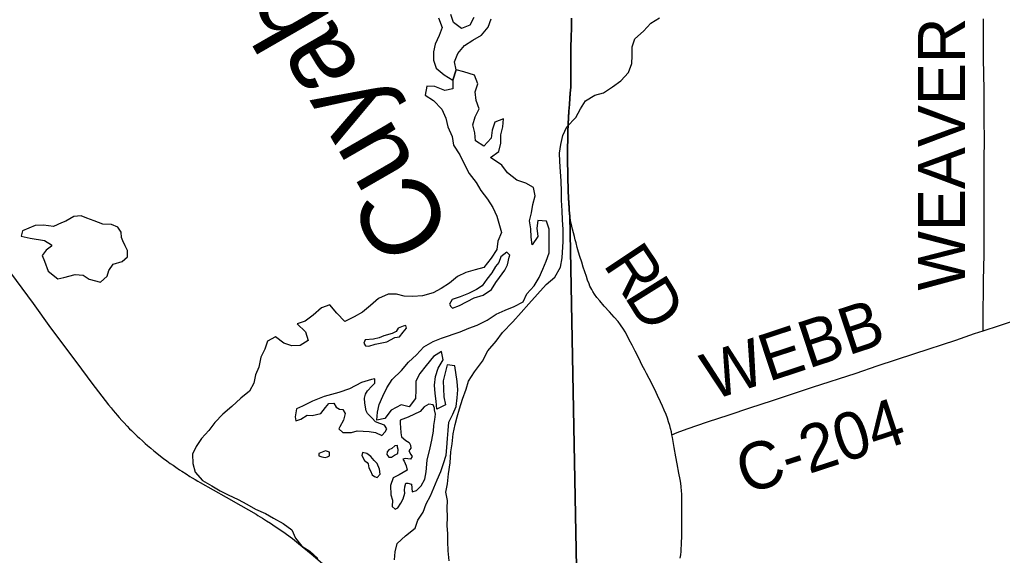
# Model space of a CAD drawing. Extents: x 0 to 34, y 0 to 22.
# Drawn here: x 4.363 to 5.549, y 18.065 to 18.712 of the extents above; entities that cross this region are included whole.
import ezdxf

# ---------------------------------------------------------------- set-up
doc = ezdxf.new("R2010")
doc.units = 0
for name, color, linetype in [('GM_X_Corporation', 7, 'Continuous'), ('GM_X_County_Road', 7, 'Continuous'), ('GM_X_County_Road_Text', 7, 'Continuous'), ('GM_X_Major_Lake', 7, 'Continuous'), ('GM_X_Major_River', 7, 'Continuous'), ('GM_X_Major_River_Text', 7, 'Continuous'), ('GM_X_Minor_Lake', 7, 'Continuous'), ('GM_X_Minor_River', 7, 'Continuous'), ('GM_X_State_Route', 7, 'Continuous'), ('GM_X_Township_Road', 7, 'Continuous'), ('GM_X_Township_Road_Text', 7, 'Continuous')]:
    doc.layers.add(name, color=color, linetype=linetype)

msp = doc.modelspace()

# ---------------------------------------------------------------- linework, layer by layer
at = {"layer": 'GM_X_Corporation'}
for points in [[(5.0372, 17.9657), (5.0273, 18.4749), (5.0269, 18.4781), (5.0266, 18.4816), (5.0264, 18.4849), (5.026, 18.4907), (5.0257, 18.4966), (5.0254, 18.5052), (5.0252, 18.5098), (5.025, 18.5176), (5.0249, 18.5239), (5.0248, 18.5304), (5.0247, 18.5364), (5.0247, 18.5429), (5.0247, 18.548), (5.0247, 18.5561), (5.0248, 18.5679), (5.025, 18.5766), (5.0254, 18.5856), (5.0258, 18.5939), (5.0263, 18.6011), (5.0269, 18.6094), (5.0275, 18.6171), (5.0279, 18.6231), (5.0284, 18.6303), (5.0286, 18.6362), (5.0287, 18.641), (5.0287, 18.6468), (5.0286, 18.6519), (5.0285, 18.6576), (5.0284, 18.6614), (5.0284, 18.6675), (5.0284, 18.6713), (5.0285, 18.6794), (5.0288, 18.6892), (5.0292, 18.7031), (5.0294, 18.7134)], [(5.0372, 17.9657), (5.0273, 18.4749), (5.0269, 18.4781), (5.0266, 18.4816), (5.0264, 18.4849), (5.026, 18.4907), (5.0257, 18.4966), (5.0254, 18.5052), (5.0252, 18.5098), (5.025, 18.5176), (5.0249, 18.5239), (5.0248, 18.5304), (5.0247, 18.5364), (5.0247, 18.5429), (5.0247, 18.548), (5.0247, 18.5561), (5.0248, 18.5679), (5.025, 18.5766), (5.0254, 18.5856), (5.0258, 18.5939), (5.0263, 18.6011), (5.0269, 18.6094), (5.0275, 18.6171), (5.0279, 18.6231), (5.0284, 18.6303), (5.0286, 18.6362), (5.0287, 18.641), (5.0287, 18.6468), (5.0286, 18.6519), (5.0285, 18.6576), (5.0284, 18.6614), (5.0284, 18.6675), (5.0284, 18.6713), (5.0285, 18.6794), (5.0288, 18.6892), (5.0292, 18.7031), (5.0294, 18.7134)], [(5.0294, 18.7134), (5.0292, 18.7031), (5.0288, 18.6892), (5.0285, 18.6794), (5.0284, 18.6713), (5.0284, 18.6675), (5.0284, 18.6614), (5.0285, 18.6576), (5.0286, 18.6519), (5.0287, 18.6468), (5.0287, 18.641), (5.0286, 18.6362), (5.0284, 18.6303), (5.0279, 18.6231), (5.0275, 18.6171), (5.0269, 18.6094), (5.0263, 18.6011), (5.0258, 18.5939), (5.0254, 18.5856), (5.025, 18.5766), (5.0248, 18.5679), (5.0247, 18.5561), (5.0247, 18.548), (5.0247, 18.5429), (5.0247, 18.5364), (5.0248, 18.5304), (5.0249, 18.5239), (5.025, 18.5176), (5.0252, 18.5098), (5.0254, 18.5052), (5.0257, 18.4966), (5.026, 18.4907), (5.0264, 18.4849), (5.0266, 18.4816), (5.0269, 18.4781), (5.0273, 18.4749), (5.0372, 17.9657)]]:
    msp.add_lwpolyline(points, dxfattribs=at)
at = {"layer": 'GM_X_County_Road'}
for points in [[(5.5262, 18.3362), (5.5263, 18.348), (5.5267, 18.3971), (5.5273, 18.4282), (5.5274, 18.4517), (5.5275, 18.4853), (5.5276, 18.499), (5.5276, 18.5419), (5.5278, 18.5679), (5.5276, 18.5897), (5.5273, 18.6313), (5.5272, 18.6413), (5.5267, 18.6692), (5.5266, 18.6847), (5.5265, 18.7126)], [(5.5262, 18.3362), (5.5459, 18.3425), (5.6054, 18.3624)], [(5.1506, 18.2108), (5.1571, 18.2134), (5.1691, 18.2178), (5.1935, 18.2262), (5.2196, 18.235), (5.2448, 18.2434), (5.272, 18.2523), (5.3033, 18.2624), (5.3204, 18.2682), (5.373, 18.2853), (5.3983, 18.294), (5.4437, 18.309), (5.4934, 18.3251), (5.5157, 18.3328), (5.5262, 18.3362)]]:
    msp.add_lwpolyline(points, dxfattribs=at)
at = {"layer": 'GM_X_Major_Lake'}
for p, q in [((4.8901, 18.651), (4.8861, 18.6387)), ((4.8901, 18.651), (4.8861, 18.6387)), ((4.9333, 18.4062), (4.927, 18.3986)), ((4.8128, 18.3328), (4.803, 18.3301)), ((4.8469, 18.239), (4.8321, 18.2321)), ((4.7706, 18.2157), (4.785, 18.2147)), ((4.7319, 18.1832), (4.7349, 18.1843)), ((4.8124, 18.1944), (4.809, 18.1925)), ((4.7841, 18.1756), (4.7846, 18.171))]:
    msp.add_line(p, q, dxfattribs=at)
for points in [[(4.9452, 18.5359), (4.9318, 18.5455), (4.9415, 18.5525), (4.9441, 18.5628), (4.944, 18.5726), (4.9465, 18.5825), (4.9472, 18.592), (4.937, 18.5881), (4.9337, 18.5782), (4.9326, 18.5687), (4.9237, 18.5591), (4.9137, 18.5655), (4.9125, 18.5749), (4.9101, 18.5848), (4.913, 18.5943), (4.9179, 18.6039), (4.9143, 18.6141), (4.9131, 18.6247), (4.9164, 18.6342), (4.9121, 18.6448), (4.8996, 18.6488), (4.8901, 18.651)], [(4.8861, 18.6387), (4.8862, 18.6281), (4.8764, 18.6261), (4.8646, 18.631), (4.8548, 18.6313), (4.8526, 18.6206), (4.8629, 18.6143), (4.8728, 18.6037), (4.8778, 18.5928), (4.8801, 18.5822), (4.8852, 18.5708)], [(4.8852, 18.5708), (4.8871, 18.5602), (4.8944, 18.5485), (4.9002, 18.5368), (4.9059, 18.5262), (4.9143, 18.5153), (4.9201, 18.5055), (4.9281, 18.4949), (4.9343, 18.4851), (4.9393, 18.4745), (4.9447, 18.4549), (4.9403, 18.4442), (4.9392, 18.4343), (4.9325, 18.424), (4.9235, 18.4126), (4.9133, 18.4099), (4.9019, 18.4064), (4.8918, 18.4017), (4.882, 18.3937), (4.8722, 18.3872), (4.8624, 18.3822), (4.8496, 18.3783), (4.8378, 18.3778), (4.8276, 18.3781), (4.8181, 18.3803), (4.8079, 18.3806), (4.7966, 18.3752), (4.7868, 18.3668), (4.777, 18.3587), (4.7669, 18.353), (4.7559, 18.3476), (4.746, 18.3577), (4.7376, 18.3675), (4.7278, 18.364), (4.7177, 18.3549), (4.7079, 18.348), (4.6981, 18.3448), (4.7083, 18.3351), (4.7115, 18.3245), (4.7017, 18.3183), (4.6918, 18.3182), (4.682, 18.3212), (4.6721, 18.3291), (4.6623, 18.3237), (4.6593, 18.3142), (4.6545, 18.3043), (4.6519, 18.2925), (4.6478, 18.283), (4.646, 18.2731), (4.6408, 18.2636), (4.6303, 18.2548), (4.6194, 18.2449), (4.6084, 18.2357), (4.5987, 18.2257), (4.5916, 18.2158), (4.5826, 18.2063), (4.5762, 18.1967), (4.5721, 18.1872), (4.5722, 18.1762), (4.5753, 18.1656), (4.5841, 18.1558), (4.5951, 18.1491), (4.6054, 18.1431), (4.6149, 18.1383), (4.627, 18.1327), (4.6377, 18.1271), (4.6479, 18.1211), (4.6601, 18.1158), (4.6696, 18.1102), (4.6814, 18.1039), (4.6917, 18.096), (4.6963, 18.0862), (4.7039, 18.0764), (4.7134, 18.0704), (4.7233, 18.0617)], [(4.8159, 18.06), (4.8166, 18.0695), (4.8191, 18.0798), (4.8292, 18.089), (4.8405, 18.0983), (4.8438, 18.1078), (4.8505, 18.1174), (4.8538, 18.1273), (4.859, 18.1372), (4.8634, 18.1468), (4.8671, 18.1563), (4.8716, 18.1666), (4.8749, 18.1762), (4.8781, 18.1861), (4.8788, 18.1956), (4.8798, 18.2062), (4.8805, 18.2161), (4.8815, 18.226), (4.8863, 18.2355), (4.89, 18.2451), (4.8914, 18.2553), (4.892, 18.2652), (4.8912, 18.2751), (4.8887, 18.294), (4.8792, 18.2951), (4.877, 18.2856), (4.8745, 18.276), (4.875, 18.2662), (4.8751, 18.2567), (4.8771, 18.2468), (4.8669, 18.2418), (4.8661, 18.2512), (4.8648, 18.2607), (4.8639, 18.2706), (4.8653, 18.2809), (4.8686, 18.2911), (4.8746, 18.3011), (4.8726, 18.3113), (4.8628, 18.3051), (4.8538, 18.2944), (4.8464, 18.2848), (4.8416, 18.2753), (4.8413, 18.265), (4.841, 18.2544), (4.8336, 18.2444), (4.8237, 18.2469), (4.8116, 18.2404), (4.8042, 18.2304), (4.7944, 18.2284), (4.7954, 18.2379), (4.7972, 18.2474), (4.8016, 18.2573), (4.8064, 18.2676), (4.8131, 18.2776), (4.824, 18.2883), (4.8326, 18.2983), (4.8423, 18.3072), (4.8513, 18.3168), (4.8626, 18.3234), (4.8724, 18.3273), (4.895, 18.3351), (4.9056, 18.3394), (4.9154, 18.343), (4.9274, 18.3492), (4.9383, 18.3565), (4.9493, 18.3612), (4.9602, 18.3655), (4.9711, 18.3713), (4.9756, 18.3809), (4.9842, 18.3905), (4.9905, 18.4004), (4.9949, 18.4107), (4.9986, 18.4203), (5.0023, 18.4302), (5.0026, 18.4397), (5.0023, 18.4587), (4.9992, 18.4685), (4.9886, 18.4695), (4.9876, 18.46), (4.9888, 18.4502), (4.9817, 18.4398), (4.9805, 18.4493), (4.9804, 18.4592), (4.9787, 18.469), (4.9809, 18.4785), (4.9827, 18.4888), (4.9856, 18.4991), (4.9836, 18.509), (4.9741, 18.5145), (4.9634, 18.5178), (4.9523, 18.5268), (4.9452, 18.5359)], [(4.927, 18.3986), (4.9217, 18.3906), (4.9146, 18.386), (4.9052, 18.3813), (4.895, 18.3771), (4.8855, 18.374), (4.8822, 18.3683), (4.8837, 18.3656), (4.8856, 18.3634), (4.8943, 18.3668), (4.912, 18.3761), (4.9226, 18.3792), (4.9328, 18.3861), (4.938, 18.3945), (4.9425, 18.4006), (4.9488, 18.4094), (4.9522, 18.4158), (4.954, 18.425), (4.9551, 18.4276), (4.9513, 18.431), (4.9442, 18.4253), (4.9416, 18.4188), (4.9375, 18.4138), (4.9333, 18.4062)], [(4.803, 18.3301), (4.7973, 18.3278), (4.7905, 18.3262), (4.7803, 18.3254), (4.7788, 18.3212), (4.7808, 18.3182), (4.7849, 18.3175), (4.7925, 18.3202), (4.8065, 18.3229), (4.8163, 18.3283), (4.8216, 18.3291), (4.8264, 18.3345), (4.8302, 18.3394), (4.8294, 18.3425), (4.826, 18.3417), (4.8203, 18.3393), (4.8177, 18.3352), (4.8128, 18.3328)], [(4.785, 18.2147), (4.7929, 18.2136), (4.8005, 18.2099), (4.8043, 18.2144), (4.8065, 18.2179), (4.8038, 18.2224), (4.7981, 18.2243), (4.7928, 18.2265), (4.7886, 18.231), (4.7833, 18.2363), (4.7814, 18.2397), (4.7798, 18.2491), (4.7794, 18.2548), (4.7808, 18.2598), (4.7831, 18.264), (4.7883, 18.2693), (4.7921, 18.2731), (4.7921, 18.2781), (4.7879, 18.2773), (4.7758, 18.2738), (4.7615, 18.2661), (4.7487, 18.2618), (4.7309, 18.2571), (4.7166, 18.2513), (4.7045, 18.2455), (4.6973, 18.2421), (4.6959, 18.2326), (4.6967, 18.2276), (4.7027, 18.2296), (4.7103, 18.2346), (4.7163, 18.2339), (4.7269, 18.2366), (4.7325, 18.2438), (4.7363, 18.2484), (4.7427, 18.2489), (4.7454, 18.2439), (4.7492, 18.2417), (4.7534, 18.2414), (4.756, 18.2364), (4.7542, 18.2285), (4.7497, 18.2205), (4.7486, 18.2178), (4.7532, 18.2137), (4.7638, 18.2137), (4.7706, 18.2157)], [(4.8321, 18.2321), (4.8227, 18.2286), (4.8227, 18.2244), (4.8228, 18.2195), (4.8232, 18.2131), (4.824, 18.2085), (4.8293, 18.204), (4.8335, 18.2014), (4.8351, 18.1984), (4.8355, 18.1946), (4.8332, 18.1915), (4.8355, 18.187), (4.8371, 18.1847), (4.8352, 18.1813), (4.8287, 18.182), (4.8257, 18.1812), (4.8273, 18.179), (4.83, 18.1733), (4.8311, 18.168), (4.8213, 18.1626), (4.8142, 18.1588), (4.8108, 18.1496), (4.8113, 18.1383), (4.8132, 18.1318), (4.8129, 18.1242), (4.8167, 18.1209), (4.8197, 18.1228), (4.8235, 18.1281), (4.8261, 18.1334), (4.8283, 18.1403), (4.8279, 18.1441), (4.8283, 18.1479), (4.8294, 18.1524), (4.832, 18.1525), (4.8362, 18.1513), (4.837, 18.1419), (4.8423, 18.1434), (4.8479, 18.1492), (4.8524, 18.1572), (4.8539, 18.1659), (4.8553, 18.1803), (4.8589, 18.1951), (4.8607, 18.2043), (4.8629, 18.2153), (4.8633, 18.2221), (4.8643, 18.2293), (4.8654, 18.2358), (4.8642, 18.2407), (4.8639, 18.243), (4.8623, 18.2471), (4.857, 18.2478), (4.8517, 18.2444), (4.8469, 18.239)], [(4.809, 18.1925), (4.8067, 18.1902), (4.8064, 18.1868), (4.8087, 18.1838), (4.8121, 18.1838), (4.8158, 18.1861), (4.8196, 18.188), (4.82, 18.1929), (4.8192, 18.196), (4.8192, 18.1979), (4.8161, 18.1975), (4.8124, 18.1944)], [(4.7349, 18.1843), (4.7371, 18.1855), (4.7371, 18.19), (4.7325, 18.1915), (4.7246, 18.188), (4.7243, 18.1854), (4.7281, 18.1843), (4.7319, 18.1832)], [(4.7846, 18.171), (4.7869, 18.1673), (4.7888, 18.1624), (4.7918, 18.1605), (4.7949, 18.1594), (4.7986, 18.1632), (4.7978, 18.1693), (4.7947, 18.1761), (4.7913, 18.1798), (4.7871, 18.1847), (4.7825, 18.1881), (4.7772, 18.1892), (4.7765, 18.1858), (4.7796, 18.1797), (4.7826, 18.1775), (4.7841, 18.1756)]]:
    msp.add_lwpolyline(points, dxfattribs=at)
at = {"layer": 'GM_X_Major_River'}
msp.add_line((4.8861, 18.6387), (4.8901, 18.651), dxfattribs=at)
msp.add_line((4.8861, 18.6387), (4.8901, 18.651), dxfattribs=at)
for points in [[(4.9113, 18.7144), (4.9068, 18.7049), (4.8966, 18.701), (4.8871, 18.7082), (4.8836, 18.718)], [(4.8689, 18.7137), (4.8732, 18.702), (4.8698, 18.6925), (4.865, 18.6822), (4.8628, 18.6727), (4.8629, 18.6628), (4.866, 18.653), (4.8755, 18.6451), (4.8861, 18.6387)], [(4.8901, 18.651), (4.8881, 18.6608), (4.8921, 18.6708), (4.9003, 18.6804), (4.9101, 18.6869), (4.9206, 18.6931), (4.9289, 18.7027), (4.9325, 18.7126)]]:
    msp.add_lwpolyline(points, dxfattribs=at)
at = {"layer": 'GM_X_Minor_Lake'}
msp.add_line((4.4636, 18.4648), (4.4534, 18.4689), dxfattribs=at)
msp.add_lwpolyline([(4.4534, 18.4689), (4.4443, 18.4722), (4.4374, 18.4748), (4.4287, 18.474), (4.4189, 18.4686), (4.414, 18.4667), (4.4042, 18.462), (4.3921, 18.4638), (4.3819, 18.4634), (4.3668, 18.4568), (4.365, 18.4504), (4.3759, 18.4482), (4.3934, 18.4453), (4.4017, 18.44), (4.4018, 18.4385), (4.3954, 18.4335), (4.3905, 18.427), (4.3932, 18.4202), (4.3978, 18.4081), (4.4093, 18.3991), (4.4168, 18.4007), (4.4304, 18.4042), (4.4399, 18.4035), (4.4471, 18.3986), (4.4608, 18.395), (4.469, 18.4022), (4.4709, 18.4091), (4.4761, 18.4167), (4.4871, 18.4198), (4.4934, 18.4256), (4.4934, 18.4331), (4.4907, 18.4388), (4.488, 18.4449), (4.4864, 18.449), (4.486, 18.4551), (4.4818, 18.4611), (4.4742, 18.4645), (4.4636, 18.4648)], dxfattribs=at)
at = {"layer": 'GM_X_Minor_River'}
for points in [[(5.0162, 18.4129), (5.018, 18.4243), (5.0194, 18.444), (5.0192, 18.4585), (5.0184, 18.4702), (5.0183, 18.4808), (5.0175, 18.4937), (5.0174, 18.504), (5.0169, 18.5172), (5.0161, 18.5282), (5.0152, 18.5404), (5.0147, 18.5506), (5.0166, 18.5612), (5.0191, 18.5719), (5.0236, 18.5825), (5.0345, 18.5936), (5.0404, 18.6039), (5.0464, 18.6138), (5.0577, 18.6207), (5.0679, 18.6234), (5.0788, 18.6307), (5.089, 18.638), (5.098, 18.648), (5.1021, 18.6586), (5.1028, 18.6681), (5.1027, 18.6787), (5.106, 18.6886), (5.1162, 18.6978), (5.1252, 18.7073), (5.1357, 18.7139)], [(4.8816, 18.0588), (4.8807, 18.0709), (4.8802, 18.0819), (4.8802, 18.0914), (4.8793, 18.1012), (4.8796, 18.1115), (4.8792, 18.1221), (4.8799, 18.1316), (4.8775, 18.1414), (4.8797, 18.1517), (4.8811, 18.1635), (4.8829, 18.1771), (4.8836, 18.1904), (4.8854, 18.1999), (4.8864, 18.212), (4.889, 18.2231), (4.8912, 18.2326), (4.8941, 18.2421), (4.8978, 18.2538), (4.9023, 18.266), (4.9049, 18.2755), (4.9123, 18.2866), (4.9221, 18.2995), (4.9284, 18.3121), (4.9385, 18.3236), (4.946, 18.3342), (4.9584, 18.3469), (4.9685, 18.3583), (4.9779, 18.3686), (4.9884, 18.3805), (4.9989, 18.3919), (5.0091, 18.4011), (5.0162, 18.4129)]]:
    msp.add_lwpolyline(points, dxfattribs=at)
at = {"layer": 'GM_X_State_Route'}
msp.add_lwpolyline([(4.3327, 18.4325), (4.3796, 18.369), (4.4006, 18.3397), (4.4323, 18.2974), (4.4504, 18.2729), (4.4706, 18.2469), (4.4736, 18.2433), (4.4761, 18.2402), (4.4788, 18.2369), (4.481, 18.2345), (4.4835, 18.2316), (4.4866, 18.228), (4.4891, 18.2254), (4.4931, 18.2212), (4.496, 18.2181), (4.4983, 18.2159), (4.5027, 18.2115), (4.5053, 18.209), (4.508, 18.2065), (4.5115, 18.2033), (4.5149, 18.2002), (4.5176, 18.1979), (4.5216, 18.1945), (4.5252, 18.1913), (4.529, 18.1884), (4.5335, 18.1848), (4.5371, 18.1821), (4.5409, 18.1794), (4.545, 18.1763), (4.5484, 18.174), (4.5519, 18.1716), (4.5562, 18.1686), (4.5591, 18.1668), (4.5643, 18.1635), (4.5688, 18.1606), (4.5715, 18.159), (4.5752, 18.1568), (4.5785, 18.1548), (4.581, 18.1533), (4.6124, 18.1356), (4.6303, 18.1255), (4.6486, 18.1148), (4.6508, 18.1134), (4.6534, 18.1119), (4.6563, 18.1101), (4.6587, 18.1086), (4.6612, 18.107), (4.666, 18.104), (4.6689, 18.1021), (4.674, 18.0987), (4.681, 18.094), (4.6927, 18.0856), (4.7, 18.0798), (4.7153, 18.067), (4.754, 18.0338)], dxfattribs=at)
at = {"layer": 'GM_X_Township_Road'}
for points in [[(5.0275, 18.4743), (5.0271, 18.4776), (5.0268, 18.4811), (5.0266, 18.4843), (5.0262, 18.4902), (5.0259, 18.4961), (5.0256, 18.5046), (5.0254, 18.5093), (5.0252, 18.517), (5.0251, 18.5234), (5.025, 18.5299), (5.0249, 18.5358), (5.0249, 18.5423), (5.0249, 18.5475), (5.0249, 18.5556), (5.025, 18.5674), (5.0252, 18.5761), (5.0256, 18.585), (5.026, 18.5934), (5.0265, 18.6006), (5.0271, 18.6088), (5.0278, 18.6165), (5.0281, 18.6226), (5.0286, 18.6297), (5.0288, 18.6356), (5.0289, 18.6404), (5.0289, 18.6462), (5.0289, 18.6514), (5.0287, 18.657), (5.0286, 18.6609), (5.0286, 18.6669), (5.0286, 18.6707), (5.0287, 18.6788), (5.029, 18.6886), (5.0294, 18.7025), (5.0297, 18.7128)], [(5.1506, 18.2108), (5.1499, 18.2142), (5.149, 18.2182), (5.148, 18.2221), (5.1466, 18.2265), (5.1452, 18.2309), (5.1435, 18.2352), (5.1413, 18.2406), (5.1393, 18.2452), (5.1369, 18.2504), (5.1333, 18.2581), (5.13, 18.2654), (5.1281, 18.2691), (5.1264, 18.2726), (5.123, 18.2788), (5.1199, 18.2846), (5.1177, 18.2887), (5.1148, 18.2945), (5.1126, 18.2987), (5.1097, 18.3047), (5.1061, 18.3118), (5.1024, 18.319), (5.0991, 18.3254), (5.0964, 18.3307), (5.0942, 18.3348), (5.0921, 18.3381), (5.0886, 18.3433), (5.0858, 18.3473), (5.0808, 18.3527), (5.0751, 18.3591), (5.069, 18.3658), (5.0637, 18.3722), (5.06, 18.3766), (5.0573, 18.3803), (5.0551, 18.3838), (5.0538, 18.3861), (5.0517, 18.3901), (5.0505, 18.3929), (5.0488, 18.3973), (5.0473, 18.4017), (5.0455, 18.4072), (5.0436, 18.4132), (5.0418, 18.4191), (5.0395, 18.4257), (5.0378, 18.4313), (5.0363, 18.4368), (5.0349, 18.4422), (5.0338, 18.4459), (5.0328, 18.45), (5.0316, 18.4546), (5.0305, 18.459), (5.0296, 18.4626), (5.0287, 18.4671), (5.0281, 18.4701), (5.0278, 18.4722), (5.0275, 18.4743)], [(5.1607, 18.0621), (5.1612, 18.0661), (5.1617, 18.0701), (5.1623, 18.0812), (5.1625, 18.0871), (5.1625, 18.1002), (5.1625, 18.1172), (5.1624, 18.1309), (5.1624, 18.139), (5.1623, 18.1431), (5.1619, 18.1479), (5.1613, 18.1522), (5.1604, 18.1569), (5.159, 18.1644), (5.1569, 18.1757), (5.1554, 18.1841), (5.1533, 18.1954), (5.1512, 18.2074), (5.1506, 18.2108)]]:
    msp.add_lwpolyline(points, dxfattribs=at)

# ---------------------------------------------------------------- texts
at = {"layer": 'GM_X_County_Road_Text'}
for s, rotation, p in [('WEAVER', 90, (5.5044, 18.3848)), ('WEBB', 18.2856, (5.1989, 18.2519)), ('C-204', 18.0885, (5.2396, 18.1384))]:
    msp.add_text(s, height=0.05682, rotation=rotation, dxfattribs=at).set_placement(p)
at = {"layer": 'GM_X_Major_River_Text'}
msp.add_text('Cuyahoga', height=0.09474, rotation=119.9689, dxfattribs=at).set_placement((4.8885, 18.4557))
at = {"layer": 'GM_X_Township_Road_Text'}
for s, rotation, p in [('R', 303.7702, (5.0667, 18.4163)), ('D', 301.9359, (5.0924, 18.3779))]:
    msp.add_text(s, height=0.0568, rotation=rotation, dxfattribs=at).set_placement(p)

doc.saveas('drawing.dxf')
